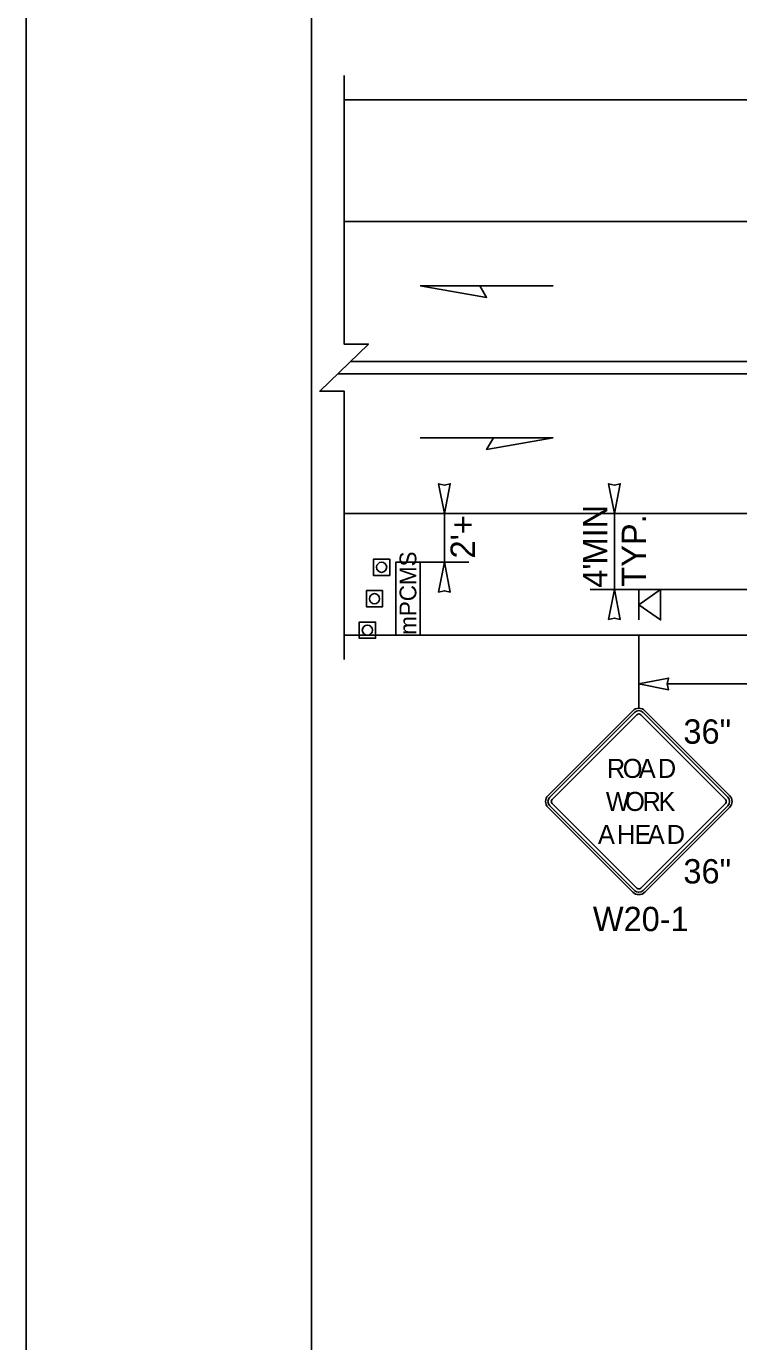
# Model space of a CAD drawing. Extents: x 99999.1 to 100095.7, y 99995 to 100010.7.
# Drawn here: x 100039.062 to 100041.405, y 100003.409 to 100007.734 of the extents above; entities that cross this region are included whole.
import ezdxf

# ---------------------------------------------------------------- set-up
doc = ezdxf.new("R2010")
doc.units = 0
for name, color, linetype in [('RD_ED_ShoulderPavedEdge', 7, 'Continuous'), ('RD_MK_LineDblYellowCenter', 7, 'Continuous'), ('RD_MK_LineEdgeWhite', 7, 'Continuous'), ('SH_GI_PlotLimits', 7, 'Continuous'), ('SH_GI_SheetBorder', 7, 'Continuous'), ('TR_SN_ConstructionSigns', 7, 'Continuous'), ('TR_WZ_PCMS', 7, 'Continuous'), ('TR_WZ_PortableSignMountBlk-Org', 7, 'Continuous'), ('TR_WZ_TrafficCone', 7, 'Continuous'), ('TR_WZ_WorkZoneDetails', 7, 'Continuous'), ('TR_WZ_WorkZoneTextCurrent', 7, 'Continuous')]:
    doc.layers.add(name, color=color, linetype=linetype)

msp = doc.modelspace()

# ---------------------------------------------------------------- linework, layer by layer
at = {"layer": 'RD_ED_ShoulderPavedEdge'}
for p, q in [((100040.1076, 100007.4923), (100055.6424, 100007.4923)), ((100040.1076, 100005.7323), (100055.6424, 100005.7323))]:
    msp.add_line(p, q, dxfattribs=at)
at = {"layer": 'RD_MK_LineDblYellowCenter'}
for p, q in [((100040.1282, 100006.6323), (100043.4767, 100006.6323)), ((100040.0869, 100006.5923), (100043.4767, 100006.5923))]:
    msp.add_line(p, q, dxfattribs=at)
at = {"layer": 'RD_MK_LineEdgeWhite'}
for p, q in [((100040.1076, 100007.0923), (100055.6424, 100007.0923)), ((100040.1076, 100006.1323), (100055.6424, 100006.1323))]:
    msp.add_line(p, q, dxfattribs=at)
at = {"layer": 'SH_GI_PlotLimits'}
msp.add_lwpolyline([(100039.0625, 99999.6875), (100056.0625, 99999.6875), (100056.0625, 100010.6875), (100039.0625, 100010.6875)], close=True, dxfattribs=at)
at = {"layer": 'SH_GI_SheetBorder'}
msp.add_line((100040, 100010.375), (100040, 100000), dxfattribs=at)
at = {"layer": 'TR_SN_ConstructionSigns'}
for p, q in [((100041.0568, 100005.4841), (100040.7783, 100005.2057)), ((100041.0623, 100005.4786), (100040.7839, 100005.2001)), ((100040.7916, 100005.1924), (100041.07, 100005.4708)), ((100041.0833, 100005.4708), (100041.3617, 100005.1924)), ((100041.3694, 100005.2001), (100041.091, 100005.4786)), ((100041.375, 100005.2057), (100041.0965, 100005.4841)), ((100040.7783, 100005.1659), (100041.0568, 100004.8875)), ((100040.7839, 100005.1714), (100041.0623, 100004.893)), ((100041.07, 100004.9007), (100040.7916, 100005.1792)), ((100041.3617, 100005.1792), (100041.0833, 100004.9007)), ((100041.091, 100004.893), (100041.3694, 100005.1714)), ((100041.0965, 100004.8875), (100041.375, 100005.1659))]:
    msp.add_line(p, q, dxfattribs=at)
for centre, radius, start, end in [((100041.0767, 100005.4642), 0.0281, 45, 135), ((100041.0767, 100005.4642), 0.0203, 45, 135), ((100041.0767, 100005.4642), 0.00937, 45, 135), ((100040.7982, 100005.1858), 0.0281, 135, 225), ((100040.7982, 100005.1858), 0.0203, 135, 225), ((100041.3551, 100005.1858), 0.0203, 315, 45), ((100041.3551, 100005.1858), 0.0281, 315, 45), ((100040.7982, 100005.1858), 0.00937, 135, 225), ((100041.3551, 100005.1858), 0.00937, 315, 45), ((100041.0767, 100004.9074), 0.00937, 225, 315), ((100041.0767, 100004.9074), 0.0281, 225, 315), ((100041.0767, 100004.9074), 0.0203, 225, 315)]:
    msp.add_arc(centre, radius, start, end, dxfattribs=at)
at = {"layer": 'TR_WZ_PCMS'}
msp.add_lwpolyline([(100040.3576, 100005.7323), (100040.3576, 100005.9723), (100040.2776, 100005.9723), (100040.2776, 100005.7323)], close=True, dxfattribs=at)
msp.add_lwpolyline([(100040.3576, 100005.7323), (100040.3576, 100005.9723), (100040.2776, 100005.9723), (100040.2776, 100005.7323), (100040.3576, 100005.7323)], dxfattribs=at)
at = {"layer": 'TR_WZ_PortableSignMountBlk-Org'}
msp.add_line((100041.0767, 100005.7824), (100041.0767, 100005.8824), dxfattribs=at)
msp.add_lwpolyline([(100041.0767, 100005.8323), (100041.1485, 100005.8824), (100041.1485, 100005.7824)], close=True, dxfattribs=at)
at = {"layer": 'TR_WZ_TrafficCone'}
for points in [[(100040.2042, 100005.9823), (100040.2576, 100005.9823), (100040.2576, 100005.929), (100040.2042, 100005.929), (100040.2042, 100005.9823)], [(100040.2042, 100005.929), (100040.2576, 100005.929), (100040.2576, 100005.9823), (100040.2042, 100005.9823), (100040.2042, 100005.929)], [(100040.1809, 100005.879), (100040.2342, 100005.879), (100040.2342, 100005.8257), (100040.1809, 100005.8257), (100040.1809, 100005.879)], [(100040.1809, 100005.8257), (100040.2342, 100005.8257), (100040.2342, 100005.879), (100040.1809, 100005.879), (100040.1809, 100005.8257)], [(100040.1576, 100005.7757), (100040.2109, 100005.7757), (100040.2109, 100005.7223), (100040.1576, 100005.7223), (100040.1576, 100005.7757)], [(100040.1576, 100005.7223), (100040.2109, 100005.7223), (100040.2109, 100005.7757), (100040.1576, 100005.7757), (100040.1576, 100005.7223)]]:
    msp.add_lwpolyline(points, dxfattribs=at)
for centre in [(100040.2309, 100005.9557), (100040.2076, 100005.8523), (100040.1842, 100005.749)]:
    msp.add_circle(centre, 0.0167, dxfattribs=at)
at = {"layer": 'TR_WZ_WorkZoneDetails'}
for p, q in [((100040.5541, 100006.8816), (100040.7952, 100006.8816)), ((100040.5987, 100006.3816), (100040.3576, 100006.3816)), ((100040.3576, 100006.1323), (100040.5176, 100006.1323)), ((100040.4376, 100006.1323), (100040.4376, 100005.9723)), ((100040.9167, 100006.1323), (100041.0767, 100006.1323)), ((100040.9967, 100005.8824), (100040.9967, 100006.1323)), ((100040.3576, 100005.9723), (100040.5176, 100005.9723)), ((100040.9167, 100005.8824), (100041.0767, 100005.8824)), ((100041.0767, 100005.8824), (100043.4767, 100005.8824)), ((100041.0767, 100005.7326), (100041.0767, 100005.4923)), ((100041.7829, 100005.5723), (100041.1704, 100005.5723))]:
    msp.add_line(p, q, dxfattribs=at)
msp.add_lwpolyline([(100040.1076, 100005.6523), (100040.1076, 100006.5349), (100040.0275, 100006.5349), (100040.1876, 100006.6898), (100040.1076, 100006.6898), (100040.1076, 100007.5723)], dxfattribs=at)
for points in [[(100040.3576, 100006.8816), (100040.5764, 100006.843), (100040.5541, 100006.8816)], [(100040.7952, 100006.3816), (100040.5764, 100006.343), (100040.5987, 100006.3816)], [(100040.4376, 100006.1323), (100040.4183, 100006.2306), (100040.4376, 100006.2261), (100040.4568, 100006.2306)], [(100040.9967, 100006.1323), (100040.9774, 100006.2306), (100040.9967, 100006.2261), (100041.0159, 100006.2306)], [(100040.4376, 100005.9723), (100040.4183, 100005.8741), (100040.4376, 100005.8786), (100040.4568, 100005.8741)], [(100040.9967, 100005.8824), (100040.9774, 100005.7841), (100040.9967, 100005.7887), (100041.0159, 100005.7841)], [(100041.0767, 100005.5723), (100041.1749, 100005.5916), (100041.1704, 100005.5723), (100041.1749, 100005.5531)]]:
    msp.add_lwpolyline(points, close=True, dxfattribs=at)

# ---------------------------------------------------------------- texts
at = {"layer": 'TR_SN_ConstructionSigns'}
for s, p in [('36"', (100041.2234, 100005.3756)), ('36"', (100041.2234, 100004.916)), ('W20-1', (100040.9257, 100004.7592))]:
    msp.add_text(s, height=0.08, rotation=360, dxfattribs=at).set_placement(p)
for s, p in [('O', (100041.0237, 100005.2631)), ('R', (100040.9716, 100005.2631)), ('A', (100041.0765, 100005.2631)), ('D', (100041.1392, 100005.2631)), ('W', (100040.9683, 100005.1545)), ('O', (100041.0316, 100005.1545)), ('R', (100041.0888, 100005.1545)), ('K', (100041.1412, 100005.1545)), ('A', (100040.9423, 100005.046)), ('H', (100041.0048, 100005.046)), ('E', (100041.0623, 100005.046)), ('A', (100041.106, 100005.046)), ('D', (100041.1685, 100005.046))]:
    msp.add_text(s, height=0.0625, dxfattribs=at).set_placement(p)
at = {"layer": 'TR_WZ_PCMS'}
msp.add_text('mPCMS', height=0.055, rotation=90, dxfattribs=at).set_placement((100040.3451, 100005.7338))
at = {"layer": 'TR_WZ_WorkZoneTextCurrent'}
for s, p in [('MIN', (100040.9727, 100005.9648)), ("2'+", (100040.5376, 100005.9846)), ('TYP.', (100041.1007, 100005.892)), ("4'", (100040.9727, 100005.8883))]:
    msp.add_text(s, height=0.08, rotation=90, dxfattribs=at).set_placement(p)

doc.saveas('drawing.dxf')
